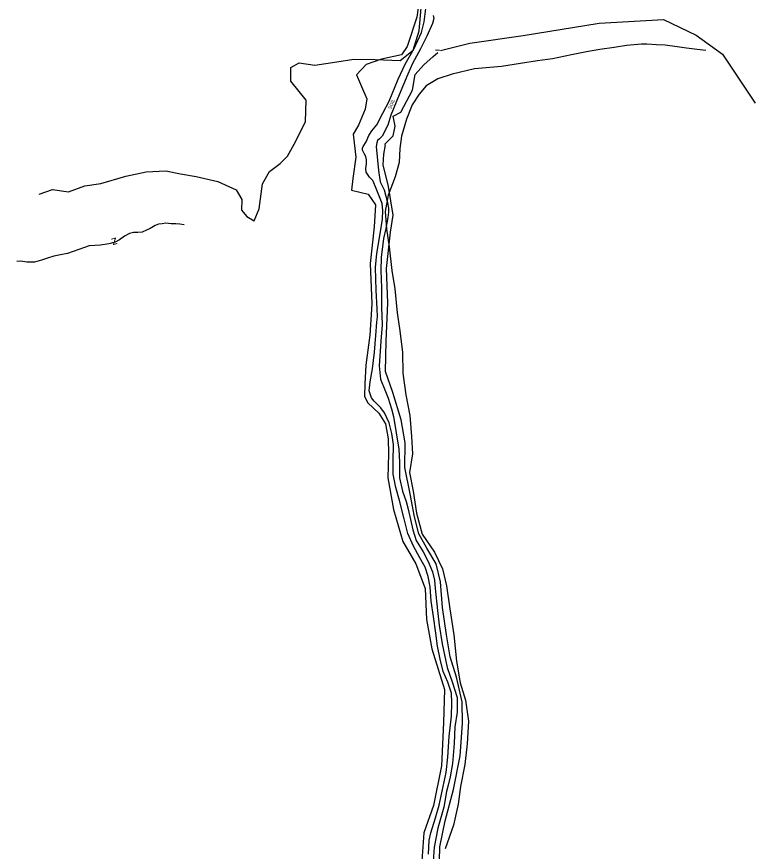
# Model space of a CAD drawing. Extents: x 2030130 to 2036320, y 723205 to 762423.
# Drawn here: x 2031526 to 2032396, y 756768 to 757751 of the extents above; entities that cross this region are included whole.
import ezdxf

# ---------------------------------------------------------------- set-up
doc = ezdxf.new("R2010")
doc.units = 0
for name, color, linetype in [('Draft_Station Labels Major', 7, 'Continuous'), ('Draft_Station Tics Major', 7, 'Continuous'), ('Old_Level_23', 7, 'Continuous'), ('Prop Alignment Horizontal', 7, 'Continuous')]:
    doc.layers.add(name, color=color, linetype=linetype)

msp = doc.modelspace()

# ---------------------------------------------------------------- linework, layer by layer
at = {"layer": 'Draft_Station Labels Major'}
for points in [[(2031937.48, 757603.64), (2031940.76, 757611.18), (2031944.35, 757616.76), (2031950.02, 757623.9), (2031956.98, 757637.4), (2031964.67, 757651.81), (2031975.11, 757677.58), (2031983.43, 757695.31), (2031994.22, 757713.72), (2032002.71, 757732.51), (2032005.73, 757745), (2032009.14, 757770.2)], [(2032016.54, 757752.75), (2032017.15, 757749.21), (2032015.62, 757743.12), (2032008.98, 757728.15), (2032001.43, 757713.11), (2031992.24, 757695.89), (2031986.41, 757683.31), (2031976.35, 757659.04), (2031966.57, 757635.1), (2031962.86, 757623.48), (2031956.53, 757610.52), (2031953.27, 757607.45), (2031951.02, 757605.23), (2031949.99, 757602.7), (2031949.31, 757598.39)], [(2032010.8, 756764.7), (2032011.74, 756781.26), (2032013.59, 756790.05), (2032019.13, 756807.79), (2032023.49, 756822.7), (2032027.2, 756839.08), (2032031.59, 756861.12), (2032033.87, 756879.05), (2032035.31, 756903.42), (2032037.89, 756927.52), (2032038.46, 756942.95), (2032037.83, 756954.36), (2032033.58, 756967.36), (2032028, 756979.89), (2032024.54, 756994.5), (2032021.49, 757009.92), (2032019.4, 757025.21), (2032016.98, 757044.89), (2032014.03, 757062.8), (2032012.76, 757079.8), (2032010.53, 757092), (2032007.06, 757102.9), (2032000.85, 757113.67), (2031993.07, 757127.43), (2031986.58, 757142.39), (2031982.19, 757159.74), (2031976.8, 757181.26), (2031972.56, 757196.77), (2031969.45, 757212.41), (2031969.45, 757227.18), (2031969.85, 757247.29), (2031967.63, 757260.39), (2031964.52, 757272.71), (2031959.22, 757284.76), (2031954.6, 757290.52), (2031950.87, 757294.55), (2031946.94, 757298.22), (2031943.7, 757302.23), (2031941.08, 757310.41), (2031942.19, 757321.09), (2031944.91, 757336.31), (2031947.42, 757355.99), (2031948.81, 757375.65), (2031950.25, 757391.38), (2031950.91, 757397.75), (2031950.29, 757407.15), (2031949.24, 757429.12), (2031948.64, 757455.8), (2031950.07, 757472.33), (2031953.93, 757495.5), (2031956.83, 757512.68), (2031957.26, 757523.03), (2031956.32, 757531.1), (2031952.62, 757541.05), (2031948.67, 757550.76), (2031945.25, 757558.13), (2031941.53, 757562.26), (2031937.48, 757567.87), (2031937.22, 757572.56), (2031938.05, 757577.98), (2031937.93, 757582.44), (2031937.08, 757586.36), (2031935.67, 757589.22), (2031934.38, 757591.75), (2031933.19, 757593.85), (2031933.2, 757596.36), (2031934.18, 757598.33), (2031937.48, 757603.64)], [(2031949.31, 757598.39), (2031951.93, 757570.11), (2031954.11, 757556.81), (2031958.65, 757547.06), (2031962.27, 757533.91), (2031963.68, 757525.72), (2031963.7, 757520.9), (2031962.84, 757514.47), (2031960.65, 757501.84), (2031957.94, 757489.95), (2031955.11, 757467.72), (2031954.97, 757452.38), (2031955.52, 757431.64), (2031955.75, 757409.18), (2031956.23, 757388.15), (2031954.88, 757369.09), (2031952.82, 757340.14), (2031954.55, 757324.24), (2031959.66, 757311.84), (2031963.61, 757301.72), (2031967.23, 757289.38), (2031969.71, 757280.23), (2031976.12, 757241.98), (2031976.88, 757226.62), (2031976.83, 757207.93), (2031980.27, 757192.42), (2031984.45, 757180.34), (2031986.96, 757171.29), (2031992.29, 757146.66), (2031996.47, 757134.18), (2032004.79, 757120.99), (2032010.41, 757109.46), (2032015.66, 757097.22), (2032018.17, 757087.36), (2032018.71, 757077.68), (2032021.47, 757051.98), (2032023.5, 757034.4), (2032027.03, 757012.73), (2032032.78, 756984.49), (2032038.83, 756967.73), (2032044.56, 756949.25), (2032044.71, 756932.22), (2032042.07, 756914.88), (2032041.34, 756895.06), (2032039.3, 756871.69), (2032036.61, 756855.77), (2032033.93, 756846.07), (2032032.2, 756838.56), (2032029.14, 756820.31), (2032021.75, 756795.49), (2032017.43, 756772.93), (2032015.77, 756745.6)]]:
    msp.add_lwpolyline(points, dxfattribs=at)
at = {"layer": 'Draft_Station Tics Major'}
msp.add_line((2032019.1, 757711.97), (2032023.79, 757711.61), dxfattribs=at)
for points in [[(2032035.84, 758056.3), (2032045.1, 758044.18), (2032046.4, 758027.95), (2032041.34, 757996.62), (2032035.86, 757964.4), (2032027.33, 757923.99), (2032012.38, 757859), (2032005.82, 757810.47), (2031997.08, 757750.45), (2031985.78, 757716.15), (2031979.18, 757706.25), (2031955.42, 757701.07), (2031937.41, 757695.04), (2031926.14, 757682.56), (2031932.12, 757669.13), (2031938.19, 757654.49), (2031936.51, 757642.19), (2031928.41, 757623.35), (2031922.37, 757612.73)], [(2031552.62, 757542.22), (2031568.04, 757547.77), (2031587.09, 757545.08), (2031606.19, 757551.8), (2031625.12, 757554.73), (2031654.48, 757563.19), (2031678.55, 757568.57), (2031701.52, 757569.49), (2031718.99, 757566.05), (2031737.23, 757562.93), (2031762.78, 757556.88), (2031784.52, 757547.32), (2031791.06, 757535.98), (2031790.77, 757523.29), (2031796.95, 757515.75), (2031805.5, 757510.84), (2031811.58, 757524.77), (2031815.39, 757554.47), (2031823.69, 757568.84), (2031836.22, 757578.31), (2031844.73, 757586.85), (2031852.81, 757600.94), (2031865.98, 757627.28), (2031866.86, 757652.89), (2031848.8, 757675.06), (2031848.97, 757691.3), (2031858.57, 757696.87), (2031876.98, 757694.09), (2031902.82, 757697.91), (2031923.05, 757700.94), (2031948.1, 757700.6), (2031977.65, 757699.61), (2031992.84, 757711.86), (2032000.08, 757734.36), (2032002.46, 757761.42)], [(2032024.87, 757711.51), (2032059.68, 757720.05), (2032122.55, 757728.95), (2032211.83, 757743.63), (2032287.79, 757747.92), (2032326.06, 757729.46), (2032357.32, 757707.06), (2032395.77, 757649.19)], [(2032337.58, 757711.51), (2032327.41, 757712.71), (2032314.89, 757714.11), (2032303.94, 757715.65), (2032289.67, 757717.71), (2032279.45, 757717.97), (2032268.1, 757718.66), (2032261.75, 757718.69), (2032243.94, 757717.37), (2032229.49, 757715.03), (2032212.68, 757712.46), (2032196.91, 757709.72), (2032179.19, 757706.12), (2032156.98, 757701.39), (2032139.47, 757699.2), (2032119.1, 757696.12), (2032096.81, 757692.6), (2032065.24, 757689.67), (2032038.72, 757683.45), (2032022.08, 757677.98), (2032008.18, 757669.84), (2031999.95, 757659.91), (2031991.83, 757647.42), (2031985.03, 757630.35), (2031979.17, 757610.43), (2031977.26, 757595.73), (2031976.42, 757579.32), (2031971.59, 757562.64), (2031963.41, 757541.12), (2031959.97, 757521.64), (2031961.58, 757501.24), (2031964.78, 757480.24), (2031967.86, 757452.32), (2031971.34, 757430.6), (2031973.98, 757402.26), (2031977.16, 757381.24), (2031980.49, 757355.69), (2031980.67, 757331.46), (2031984.38, 757305.86), (2031988.77, 757281.62), (2031990.94, 757256.62), (2031992.14, 757236.36), (2031988.73, 757214.3), (2031992.88, 757192.4), (2031996.92, 757166.49), (2032003.39, 757141.85), (2032018.02, 757120.39), (2032027.55, 757100.8), (2032032.24, 757080.71), (2032036.2, 757053.73), (2032040.59, 757023.17), (2032043.93, 756992.3), (2032048.14, 756966.66), (2032054.53, 756946.16), (2032057.88, 756921.28), (2032056.59, 756894.88), (2032053.69, 756870.26), (2032048.54, 756844.47), (2032045.8, 756823.87), (2032040.39, 756799.07), (2032030.48, 756771.11)], [(2031959.26, 757600.73), (2031969.38, 757610.69), (2031971.59, 757622.31), (2031969.34, 757634.18), (2031978.18, 757638.7), (2031992.02, 757664.46), (2031995.27, 757683.15), (2032005.24, 757694.32), (2032016.4, 757704.19), (2032021.73, 757709.08)], [(2031922.37, 757612.73), (2031925.39, 757585.66), (2031921.82, 757560.4), (2031920.33, 757546.9), (2031939.86, 757542.12), (2031948.45, 757529.56), (2031946.77, 757503.84), (2031942.34, 757460.3), (2031944.19, 757412.81), (2031942, 757375.96), (2031937.01, 757340.79), (2031936.03, 757318.72), (2031935.62, 757303.94), (2031939.59, 757296.34), (2031952.3, 757284.18), (2031960.12, 757271.81), (2031963.38, 757253.93), (2031963.66, 757236.17), (2031962.85, 757208.23), (2031969.57, 757170.8), (2031980.83, 757133.07), (2031996.07, 757106.62), (2032007.1, 757077.79), (2032008.56, 757041.05), (2032014.83, 757006.75), (2032029.84, 756958.85), (2032028.56, 756919.96), (2032026.07, 756868.71), (2032016.87, 756822.12), (2032005.61, 756790.1), (2032002.28, 756746.09)], [(2032022.99, 756725.06), (2032024.12, 756773.45), (2032030.65, 756804.22), (2032040.42, 756840.82), (2032048.18, 756880.73), (2032050.83, 756918.68), (2032050.47, 756944.3), (2032044.08, 756973.2), (2032036.34, 756997.41), (2032032, 757023.2), (2032027.58, 757055.23), (2032025.11, 757085.39), (2032019.84, 757106.58), (2032008.77, 757125.37), (2031999.36, 757141.95), (2031994.47, 757162.24), (2031989.23, 757189.25), (2031983.16, 757220.29), (2031983.44, 757249.36), (2031978.57, 757276.29), (2031968.76, 757308.44), (2031960.4, 757333.4), (2031960.88, 757369.06), (2031963.08, 757414.16), (2031961.27, 757454.4), (2031966.32, 757497.19), (2031969.49, 757517.52), (2031963.64, 757551.11), (2031957.45, 757576.75), (2031958.4, 757589.12), (2031960.2, 757600.19)]]:
    msp.add_lwpolyline(points, dxfattribs=at)
at = {"layer": 'Prop Alignment Horizontal'}
msp.add_lwpolyline([(2031723.28, 757506.12), (2031718.22, 757506.99), (2031713.41, 757507.32), (2031708.03, 757507.15), (2031701.73, 757507.8), (2031697.24, 757507.39), (2031693.08, 757506.83), (2031688.87, 757505.15), (2031683, 757501.75), (2031678.68, 757499.82), (2031673.71, 757497.34), (2031668.54, 757497.13), (2031663.49, 757497.1), (2031658.73, 757496), (2031652.87, 757492.52), (2031647.06, 757488.26), (2031642.11, 757485.59), (2031634.45, 757483.66), (2031624.64, 757481.97), (2031618.18, 757481.83), (2031611.35, 757481.34), (2031605.87, 757479.35), (2031598.97, 757476.85), (2031585.66, 757472.24), (2031577.49, 757470.83), (2031569.61, 757469.19), (2031562.08, 757466.67), (2031555.29, 757464.36), (2031547, 757462.11), (2031542.71, 757461.9), (2031537.86, 757462.18), (2031533.4, 757462.83), (2031529.97, 757463.41), (2031525.98, 757462.97)], dxfattribs=at)

# ---------------------------------------------------------------- texts
at = {"layer": 'Old_Level_23'}
msp.add_text('SOIL', height=4, rotation=67.70289, dxfattribs=at).set_placement((2031966.98, 757641.75))
at = {"layer": 'Prop Alignment Horizontal'}
msp.add_text('z', height=10, rotation=195.6824, dxfattribs=at).set_placement((2031643.18, 757491.18))

doc.saveas('drawing.dxf')
